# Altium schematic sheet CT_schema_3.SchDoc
size 287 x 169 mm
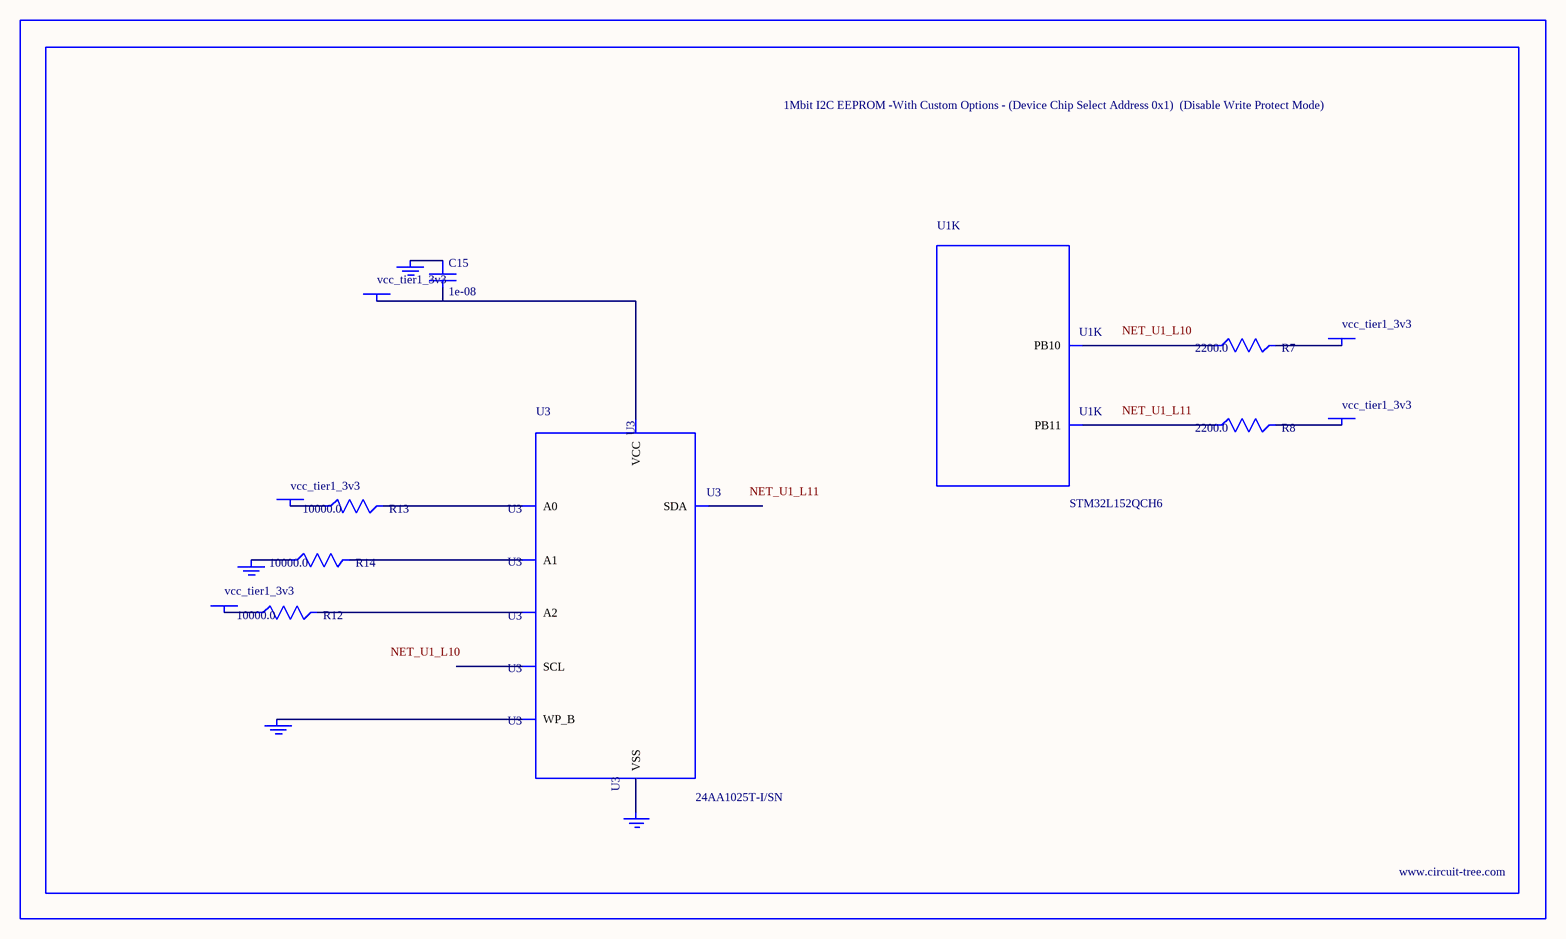
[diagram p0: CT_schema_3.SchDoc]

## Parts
BORDER2  (no value)
C15  1e-08  [C0402]
GND_INSTANCE_2_0  (no value)
GND_INSTANCE_2_1  (no value)
GND_INSTANCE_2_2  (no value)
GND_INSTANCE_2_3  (no value)
POWER_INSTANCE_2_0  vcc_tier1_3v3
POWER_INSTANCE_2_1  vcc_tier1_3v3
POWER_INSTANCE_2_2  vcc_tier1_3v3
POWER_INSTANCE_2_3  vcc_tier1_3v3
POWER_INSTANCE_2_4  vcc_tier1_3v3
R7  2200.0  [R0603]
R8  2200.0  [R0603]
R12  10000.0  [R0603]
R13  10000.0  [R0603]
R14  10000.0  [R0603]
U1  STM32L152QCH6  [UFBGA132]  (part K of 12)
U3  24AA1025T-I/SN  [SOIC-8]

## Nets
NetC15_1: C15.1 GND_INSTANCE_2_2.0(GND)
NetC15_2: C15.2 POWER_INSTANCE_2_2.0(PWR) U3.8(VCC)
NetGND_INSTANCE_2_0_0: GND_INSTANCE_2_0.0(GND) R14.1
NetGND_INSTANCE_2_1_0: GND_INSTANCE_2_1.0(GND) U3.7(WP_B)
NetGND_INSTANCE_2_3_0: GND_INSTANCE_2_3.0(GND) U3.4(VSS)
NetPOWER_INSTANCE_2_0_0: POWER_INSTANCE_2_0.0(PWR) R13.1
NetPOWER_INSTANCE_2_1_0: POWER_INSTANCE_2_1.0(PWR) R12.1
NetPOWER_INSTANCE_2_3_0: POWER_INSTANCE_2_3.0(PWR) R7.2
NetPOWER_INSTANCE_2_4_0: POWER_INSTANCE_2_4.0(PWR) R8.2
NetR7_1: R7.1 U1.L10(PB10)
NetR8_1: R8.1 U1.L11(PB11)
NetR12_2: R12.2 U3.3(A2)
NetR13_2: R13.2 U3.1(A0)
NetR14_2: R14.2 U3.2(A1)

Not connected (* = marked no-connect by the designer): U3 5(SDA) 6(SCL)

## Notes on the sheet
- Labels drawn without touching a wire or pin: NET_U1_L10, NET_U1_L11

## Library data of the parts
BORDER2 = BORDER_PAGE2
C15 = C0402C103K3RAC
GND_INSTANCE_2_0-GND_INSTANCE_2_3 = GND
POWER_INSTANCE_2_0-POWER_INSTANCE_2_4 = PWR
R7 R8 = RC0603JR-072K2L
R12-R14 = RC0603JR-0710KL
